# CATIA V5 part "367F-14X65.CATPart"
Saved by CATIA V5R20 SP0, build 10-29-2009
Part number: 367F-14X65
Definition: NONE
Nomenclature: 367F-14X65
Source: Unknown
Description: 367F-14X65
Bounding box of the stored display mesh (mm): x 0 to 65, y -14 to 14, z -14 to 14
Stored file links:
  C:\Users\Utente\Desktop\IO LAVORO\3D X SITO CF\X SITO\PLASTICA\3D files 367\367F-14X65.CATPart
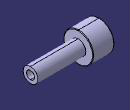
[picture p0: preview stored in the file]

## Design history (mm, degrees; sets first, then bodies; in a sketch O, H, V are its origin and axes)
Body1 "367F-14X65" (main body)
  Solid1: solid without history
